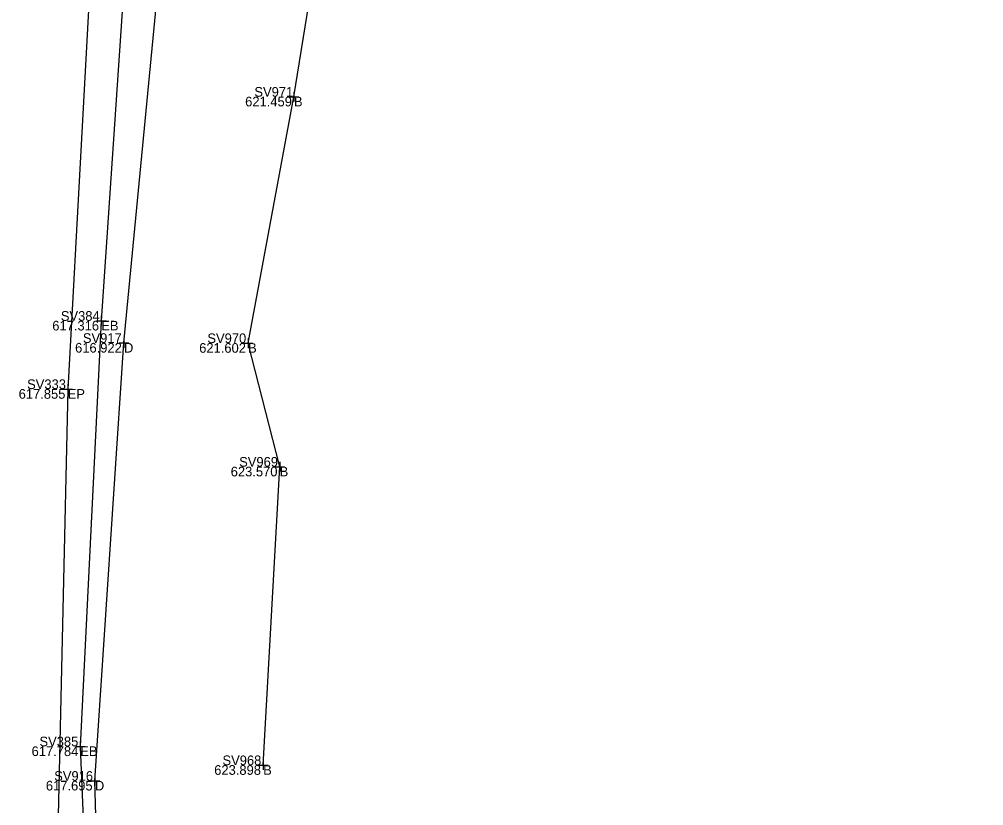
# Model space of a CAD drawing. Extents: x -2 to 1979875, y -2 to 232027.
# Drawn here: x 1978757.35 to 1978807.19, y 230801.2 to 230841.86 of the extents above; entities that cross this region are included whole.
import ezdxf

# ---------------------------------------------------------------- set-up
doc = ezdxf.new("R2010")
doc.units = 0
for name, color, linetype in [('_CIVIL_CONSTRUCTION', 7, 'Continuous'), ('DR_X_Ditch', 7, 'Continuous'), ('GE_P_Alignment', 7, 'Continuous'), ('GE_X_Alignment', 7, 'Continuous'), ('GE_X_Alignment_1000_Stations', 7, 'Continuous'), ('GE_X_Alignment_100_Curve_Data', 7, 'Continuous'), ('GE_X_Alignment_100_Stations', 7, 'Continuous'), ('SC_Scratch1', 7, 'Continuous')]:
    doc.layers.add(name, color=color, linetype=linetype)

msp = doc.modelspace()

# ---------------------------------------------------------------- linework, layer by layer
at = {"layer": 'DR_X_Ditch'}
msp.add_lwpolyline([(1978769.61, 230735.533), (1978764.556, 230757.762), (1978761.888, 230780.52), (1978761.255, 230802.491), (1978762.758, 230825.129), (1978765.137, 230850.029), (1978768.569, 230875.252), (1978770.473, 230901.75), (1978772.394, 230926.88), (1978774.225, 230946.118), (1978776.188, 230970.1), (1978776.947, 230991.277), (1978778.808, 231013.722), (1978780.679, 231036.008), (1978780.852, 231047.689), (1978785.42, 231078.945), (1978790.697, 231097.051), (1978792.307, 231119.545), (1978794.395, 231141.248), (1978795.023, 231162.503), (1978796.552, 231185.182), (1978801.304, 231199.708)], dxfattribs=at)
at = {"layer": 'GE_P_Alignment'}
msp.add_lwpolyline([(1978769.951, 230803.3), (1978770.804, 230818.73), (1978769.172, 230825.121), (1978771.54, 230837.858), (1978774.593, 230856.702), (1978777.309, 230875.323), (1978778.206, 230900.393), (1978780.194, 230917.861), (1978782.495, 230932.89), (1978782.493, 230947.115), (1978785.767, 230964.209), (1978787.856, 230986.866), (1978787.326, 231009.356), (1978787.324, 231025.342), (1978791.304, 231037.316), (1978793.971, 231062.015), (1978792.008, 231077.675), (1978794.496, 231103.739), (1978796.727, 231125.192), (1978800.775, 231143.28), (1978803.614, 231161.931), (1978803.663, 231181.675), (1978807.191, 231198.311), (1978806.504, 231203.464)], dxfattribs=at)
at = {"layer": 'GE_X_Alignment_1000_Stations'}
msp.add_lwpolyline([(1978785.568, 231251.827), (1978784.19, 231242.096), (1978782.784, 231222.648), (1978782.32, 231202.663), (1978780.702, 231177.057), (1978778.946, 231150.803), (1978777.805, 231126.797), (1978776.986, 231106.931), (1978775.705, 231085.257), (1978774.572, 231063.753), (1978773.517, 231041.76), (1978772.029, 231016.51), (1978770.7, 230994.507), (1978769.257, 230972.092), (1978767.73, 230948.595), (1978766.192, 230924.232), (1978764.603, 230899.039), (1978762.827, 230873.547), (1978761.273, 230848.668), (1978759.848, 230822.744), (1978759.345, 230799.915), (1978760.114, 230777.862), (1978762.938, 230755.551), (1978769.839, 230729.514)], dxfattribs=at)
at = {"layer": 'GE_X_Alignment_100_Curve_Data'}
for p, q in [((1978771.29, 230837.858), (1978771.79, 230837.858)), ((1978771.54, 230838.108), (1978771.54, 230837.608)), ((1978771.54, 230837.858), (1978771.54, 230837.858)), ((1978761.583, 230826.523), (1978761.583, 230826.023)), ((1978761.333, 230826.273), (1978761.833, 230826.273)), ((1978761.583, 230826.273), (1978761.583, 230826.273)), ((1978762.758, 230825.379), (1978762.758, 230824.879)), ((1978769.172, 230825.371), (1978769.172, 230824.871)), ((1978762.508, 230825.129), (1978763.008, 230825.129)), ((1978762.758, 230825.129), (1978762.758, 230825.129)), ((1978768.922, 230825.121), (1978769.422, 230825.121)), ((1978769.172, 230825.121), (1978769.172, 230825.121)), ((1978759.848, 230822.994), (1978759.848, 230822.494)), ((1978759.598, 230822.744), (1978760.098, 230822.744)), ((1978759.848, 230822.744), (1978759.848, 230822.744)), ((1978770.804, 230818.98), (1978770.804, 230818.48)), ((1978770.554, 230818.73), (1978771.054, 230818.73)), ((1978770.804, 230818.73), (1978770.804, 230818.73)), ((1978760.498, 230804.521), (1978760.498, 230804.021)), ((1978760.248, 230804.271), (1978760.748, 230804.271)), ((1978760.498, 230804.271), (1978760.498, 230804.271)), ((1978769.951, 230803.55), (1978769.951, 230803.05)), ((1978769.701, 230803.3), (1978770.201, 230803.3)), ((1978769.951, 230803.3), (1978769.951, 230803.3)), ((1978761.005, 230802.491), (1978761.505, 230802.491)), ((1978761.255, 230802.741), (1978761.255, 230802.241)), ((1978761.255, 230802.491), (1978761.255, 230802.491))]:
    msp.add_line(p, q, dxfattribs=at)
at = {"layer": 'SC_Scratch1'}
msp.add_lwpolyline([(1978787.694, 231249.601), (1978785.48, 231226.833), (1978784.558, 231206.407), (1978783.016, 231187.193), (1978782.112, 231167.584), (1978780.51, 231145.937), (1978779.287, 231125.907), (1978778.425, 231108.773), (1978777.775, 231087.524), (1978776.748, 231064.782), (1978775.35, 231040.582), (1978774.462, 231016.281), (1978772.549, 230990.683), (1978771.051, 230965.635), (1978769.086, 230942.407), (1978767.324, 230917.989), (1978765.95, 230893.701), (1978764.896, 230870.53), (1978763.088, 230848.633), (1978761.583, 230826.273), (1978760.498, 230804.271), (1978761.5, 230780.247), (1978763.845, 230755.469), (1978770.352, 230731.454)], dxfattribs=at)

# ---------------------------------------------------------------- texts
at = {"layer": '_CIVIL_CONSTRUCTION'}
for s, p in [('621.459', (1978769.019, 230837.358)), ('617.316', (1978759.051, 230825.773)), ('616.922', (1978760.23, 230824.629)), ('621.602', (1978766.644, 230824.621)), ('617.855', (1978757.313, 230822.244)), ('623.570', (1978768.274, 230818.23)), ('617.784', (1978757.982, 230803.771)), ('623.898', (1978767.421, 230802.8)), ('617.695', (1978758.72, 230801.991))]:
    msp.add_text(s, height=0.5, dxfattribs=at).set_placement(p)
at = {"layer": 'GE_X_Alignment'}
for s, p in [('SV971', (1978769.497, 230837.858)), ('SV384', (1978759.494, 230826.273)), ('SV917', (1978760.633, 230825.129)), ('SV970', (1978767.068, 230825.121)), ('SV333', (1978757.75, 230822.744)), ('SV969', (1978768.71, 230818.73)), ('SV385', (1978758.389, 230804.271)), ('SV968', (1978767.848, 230803.3)), ('SV916', (1978759.15, 230802.491))]:
    msp.add_text(s, height=0.5, dxfattribs=at).set_placement(p)
at = {"layer": 'GE_X_Alignment_100_Stations'}
for s, p in [('B', (1978771.54, 230837.358)), ('EB', (1978761.583, 230825.773)), ('D', (1978762.758, 230824.629)), ('B', (1978769.172, 230824.621)), ('EP', (1978759.848, 230822.244)), ('B', (1978770.804, 230818.23)), ('EB', (1978760.498, 230803.771)), ('B', (1978769.951, 230802.8)), ('D', (1978761.255, 230801.991))]:
    msp.add_text(s, height=0.5, dxfattribs=at).set_placement(p)

doc.saveas('drawing.dxf')
